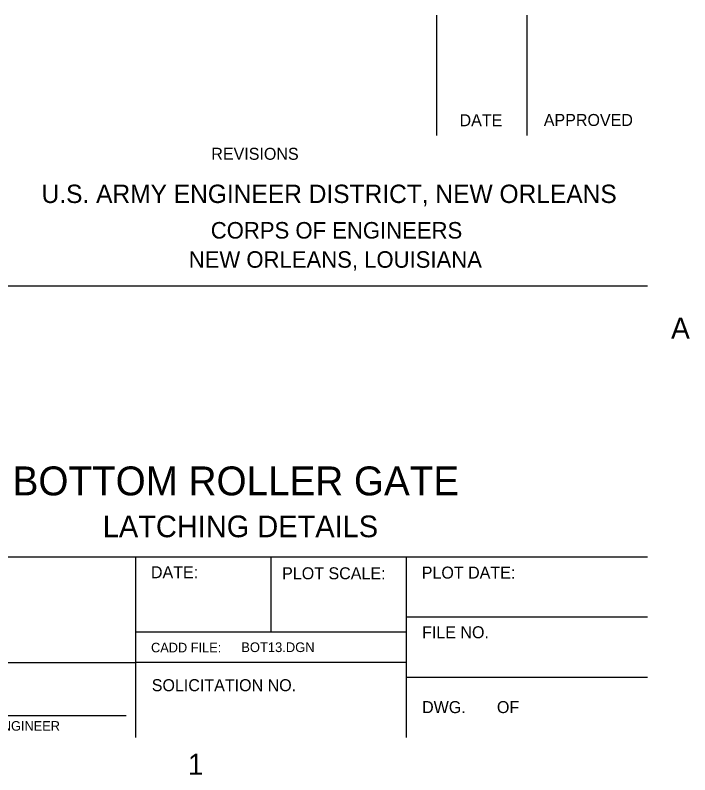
# Model space of a CAD drawing. Extents: x 0 to 53.3, y -2.9 to 37.3.
# Drawn here: x 24.18 to 24.647, y -2.889 to -2.363 of the extents above; entities that cross this region are included whole.
import ezdxf

# ---------------------------------------------------------------- set-up
doc = ezdxf.new("R2010")
doc.units = 0
doc.layers.add('Level 1', color=7, linetype='Continuous')
doc.layers.add('Level 2', color=7, linetype='Continuous')

msp = doc.modelspace()

# ---------------------------------------------------------------- linework, layer by layer
at = {"layer": 'Level 1'}
for p, q in [((24.47178, -2.44647), (24.47178, -2.36314)), ((24.53428, -2.44647), (24.53428, -2.36314)), ((24.61761, -2.55064), (24.07595, -2.55064)), ((24.61761, -2.73814), (24.07595, -2.73814)), ((24.26345, -2.86314), (24.26345, -2.73814)), ((24.3572, -2.79022), (24.3572, -2.73814)), ((24.45095, -2.86314), (24.45095, -2.73814)), ((24.61761, -2.77981), (24.45095, -2.77981)), ((24.45095, -2.79022), (24.26345, -2.79022)), ((24.07595, -2.81106), (24.26345, -2.81106)), ((24.45095, -2.81106), (24.26345, -2.81106)), ((24.61761, -2.82147), (24.45095, -2.82147)), ((24.08155, -2.84786), (24.2568, -2.84786))]:
    msp.add_line(p, q, dxfattribs=at)

# ---------------------------------------------------------------- texts
for s, height, p in [('DATE', 0.008302, (24.48757, -2.43999)), ('APPROVED', 0.008302, (24.54588, -2.43982)), ('REVISIONS', 0.008302, (24.31573, -2.46322)), ('U.S. ARMY ENGINEER DISTRICT, NEW ORLEANS', 0.0126979, (24.19823, -2.49312)), ('CORPS OF ENGINEERS', 0.0114281, (24.31536, -2.51773)), ('NEW ORLEANS, LOUISIANA', 0.0114281, (24.30011, -2.53793)), ('A', 0.0146, (24.63397, -2.58703)), ('DATE:', 0.008302, (24.27394, -2.75283)), ('PLOT SCALE:', 0.0083021, (24.36475, -2.75356)), ('PLOT DATE:', 0.008302, (24.4614, -2.75308)), ('FILE NO.', 0.008302, (24.46163, -2.79438)), ('CADD FILE:', 0.006604, (24.27402, -2.8041)), ('SOLICITATION NO.', 0.0083021, (24.27451, -2.831)), ('DWG.       OF', 0.0083021, (24.46163, -2.84617)), ('DESIGN ENGINEER', 0.0066042, (24.12853, -2.85833)), ('1', 0.0146, (24.29949, -2.88888))]:
    msp.add_text(s, height=height, dxfattribs=at).set_placement(p)
at = {"layer": 'Level 2'}
for s, height, p in [('BOTTOM ROLLER GATE', 0.02, (24.1782, -2.69547)), ('LATCHING DETAILS', 0.0149998, (24.2406, -2.72445)), ('BOT13.DGN', 0.006698, (24.33647, -2.80393))]:
    msp.add_text(s, height=height, dxfattribs=at).set_placement(p)

doc.saveas('drawing.dxf')
